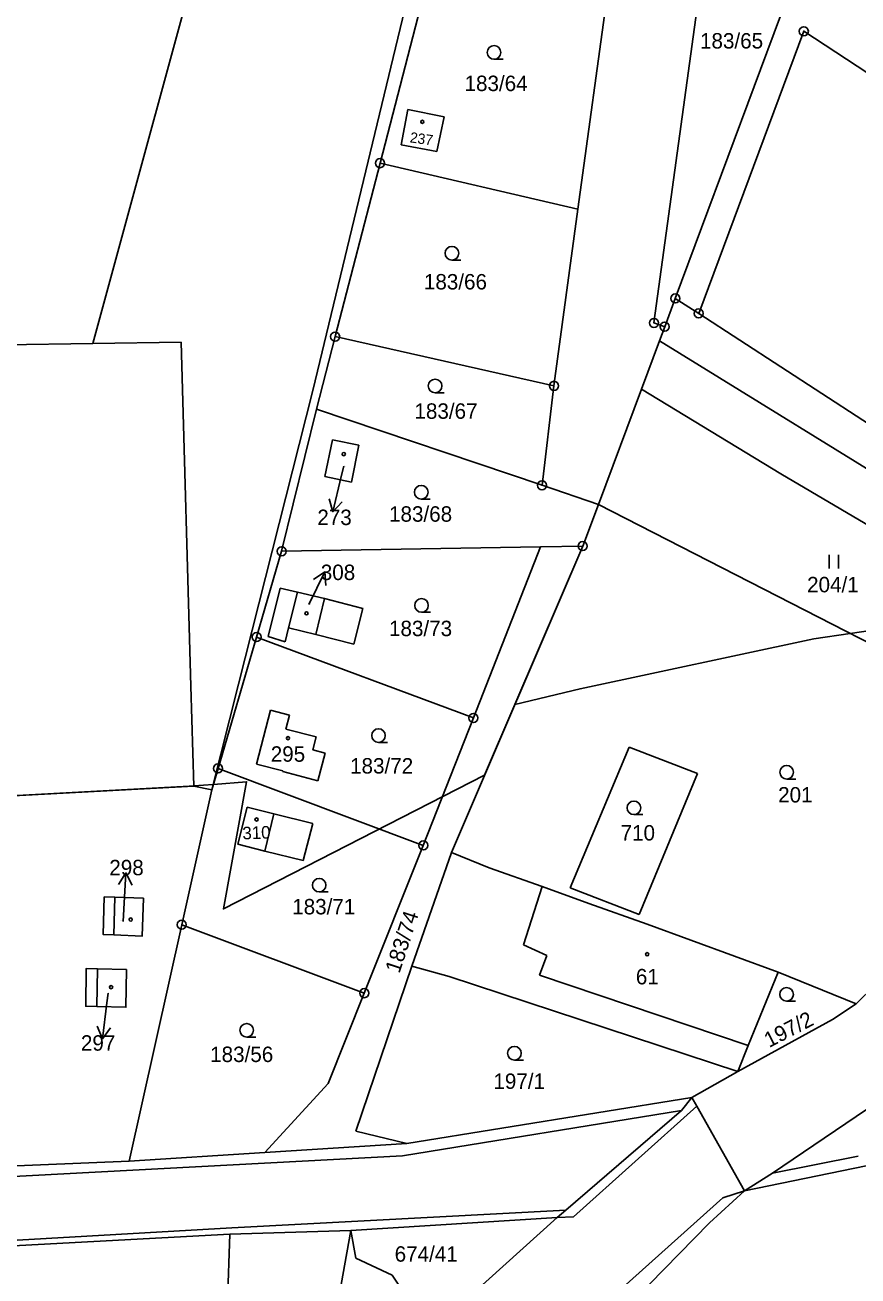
# Model space of a CAD drawing. Extents: x -747333 to -745433, y -1133152 to -1130600.
# Drawn here: x -746813.1 to -746721.3, y -1132285.5 to -1132147.6 of the extents above; entities that cross this region are included whole.
import ezdxf

# ---------------------------------------------------------------- set-up
doc = ezdxf.new("R2010")
doc.units = 0
for name, color, linetype in [('Vrstva 1', 7, 'Continuous'), ('Vrstva 16', 7, 'Continuous'), ('Vrstva 18', 7, 'Continuous'), ('Vrstva 19', 7, 'Continuous'), ('Vrstva 24', 7, 'Continuous'), ('Vrstva 25', 7, 'Continuous'), ('Vrstva 3', 7, 'Continuous'), ('Vrstva 37', 7, 'Continuous'), ('Vrstva 4', 7, 'Continuous'), ('Vrstva 52', 7, 'Continuous'), ('Vrstva 6', 7, 'Continuous')]:
    doc.layers.add(name, color=color, linetype=linetype)

msp = doc.modelspace()

# ---------------------------------------------------------------- linework, layer by layer
at = {"layer": 'Vrstva 1'}
for p, q in [((-746779.23, -1132193.32), (-746780.05, -1132197.37)), ((-746776.31, -1132193.91), (-746779.23, -1132193.32)), ((-746777.12, -1132197.98), (-746776.31, -1132193.91)), ((-746780.05, -1132197.37), (-746777.12, -1132197.98)), ((-746787.59, -1132215.05), (-746784.83, -1132205.6)), ((-746784.83, -1132205.6), (-746756.31, -1132205.11)), ((-746756.31, -1132205.11), (-746763.69, -1132223.97)), ((-746756.31, -1132205.11), (-746751.65, -1132205.03)), ((-746786.31, -1132214.99), (-746785, -1132209.67)), ((-746785, -1132209.67), (-746783.07, -1132210.11)), ((-746783.07, -1132210.11), (-746780.12, -1132210.8)), ((-746780.12, -1132210.8), (-746775.87, -1132211.89)), ((-746775.87, -1132211.89), (-746776.88, -1132215.82)), ((-746784.07, -1132214.03), (-746784.43, -1132215.59)), ((-746781.07, -1132214.77), (-746784.07, -1132214.03)), ((-746791.83, -1132229.53), (-746787.59, -1132215.05)), ((-746763.69, -1132223.97), (-746787.59, -1132215.05)), ((-746784.43, -1132215.59), (-746786.31, -1132214.99)), ((-746776.88, -1132215.82), (-746781.07, -1132214.77)), ((-746787.58, -1132229.04), (-746786.06, -1132223.12)), ((-746786.06, -1132223.12), (-746783.97, -1132223.66)), ((-746783.97, -1132223.66), (-746784.36, -1132225.19)), ((-746769.22, -1132238.01), (-746763.69, -1132223.97)), ((-746784.36, -1132225.19), (-746781.01, -1132226.05)), ((-746781.01, -1132226.05), (-746781.38, -1132227.48)), ((-746781.38, -1132227.48), (-746780.03, -1132227.83)), ((-746780.03, -1132227.83), (-746780.82, -1132230.88)), ((-746792.52, -1132231.9), (-746791.83, -1132229.53)), ((-746791.83, -1132229.53), (-746769.22, -1132238.01)), ((-746784.68, -1132229.78), (-746787.58, -1132229.04)), ((-746784.71, -1132229.88), (-746784.68, -1132229.78)), ((-746780.82, -1132230.88), (-746784.71, -1132229.88)), ((-746792.52, -1132231.9), (-746795.83, -1132246.75)), ((-746789.66, -1132237.89), (-746788.62, -1132233.78)), ((-746788.62, -1132233.78), (-746785.69, -1132234.52)), ((-746785.69, -1132234.52), (-746781.4, -1132235.6)), ((-746781.4, -1132235.6), (-746782.44, -1132239.69)), ((-746786.66, -1132238.64), (-746789.66, -1132237.89)), ((-746782.44, -1132239.69), (-746786.66, -1132238.64)), ((-746775.72, -1132254.29), (-746769.22, -1132238.01)), ((-746795.83, -1132246.75), (-746801.64, -1132272.79)), ((-746795.83, -1132246.75), (-746775.72, -1132254.29)), ((-746775.72, -1132254.29), (-746779.69, -1132264.25)), ((-746779.69, -1132264.25), (-746786.69, -1132271.84)), ((-746771.04, -1132270.84), (-746786.69, -1132271.84)), ((-746786.69, -1132271.84), (-746801.64, -1132272.79))]:
    msp.add_line(p, q, dxfattribs=at)
for points in [[(-746736.6, -1132128.06), (-746743.8, -1132180.44)], [(-746767.86, -1132139.21), (-746773.98, -1132162.83)], [(-746748.85, -1132143.55), (-746752.17, -1132167.89)], [(-746741.45, -1132177.74), (-746729.85, -1132146.61)], [(-746727.28, -1132148.3), (-746738.86, -1132179.39)], [(-746706, -1132162.26), (-746727.28, -1132148.3)], [(-746771.66, -1132160.8), (-746770.91, -1132156.92)], [(-746770.91, -1132156.92), (-746766.92, -1132157.72)], [(-746766.92, -1132157.72), (-746767.74, -1132161.56)], [(-746767.74, -1132161.56), (-746771.66, -1132160.8)], [(-746773.98, -1132162.83), (-746778.93, -1132181.95)], [(-746752.17, -1132167.89), (-746773.98, -1132162.83)], [(-746752.17, -1132167.89), (-746754.82, -1132187.37)], [(-746742.61, -1132180.85), (-746741.45, -1132177.74)], [(-746738.86, -1132179.39), (-746741.45, -1132177.74)], [(-746738.86, -1132179.39), (-746702.69, -1132202.89)], [(-746743.8, -1132180.44), (-746742.61, -1132180.85)], [(-746742.61, -1132180.85), (-746743.19, -1132182.42)], [(-746825.13, -1132182.99), (-746805.63, -1132182.7)], [(-746805.63, -1132182.7), (-746795.89, -1132182.56)], [(-746795.89, -1132182.56), (-746794.83, -1132220.45)], [(-746778.93, -1132181.95), (-746781, -1132189.93)], [(-746754.82, -1132187.37), (-746778.93, -1132181.95)], [(-746743.19, -1132182.42), (-746745.18, -1132187.75)], [(-746756.13, -1132198.33), (-746754.82, -1132187.37)], [(-746745.18, -1132187.75), (-746749.91, -1132200.43)], [(-746781, -1132189.93), (-746784.83, -1132205.6)], [(-746781, -1132189.93), (-746756.13, -1132198.33)], [(-746749.91, -1132200.43), (-746756.13, -1132198.33)], [(-746751.65, -1132205.03), (-746749.91, -1132200.43)], [(-746693.83, -1132229.18), (-746749.91, -1132200.43)], [(-746751.65, -1132205.03), (-746766.12, -1132238.78)], [(-746794.83, -1132220.45), (-746794.52, -1132231.47)], [(-746753.02, -1132242.69), (-746746.53, -1132227.19)], [(-746746.53, -1132227.19), (-746739, -1132230.07)], [(-746739, -1132230.07), (-746745.42, -1132245.64)], [(-746844.62, -1132234.18), (-746794.52, -1132231.47)], [(-746794.52, -1132231.47), (-746792.52, -1132231.9)], [(-746766.12, -1132238.78), (-746770.48, -1132251.33)], [(-746761.95, -1132240.48), (-746766.12, -1132238.78)], [(-746756.12, -1132242.54), (-746761.95, -1132240.48)], [(-746750.97, -1132244.4), (-746756.12, -1132242.54)], [(-746745.42, -1132245.64), (-746753.02, -1132242.69)], [(-746721.51, -1132255.46), (-746709.03, -1132243.21)], [(-746803.33, -1132247.87), (-746804.5, -1132247.82), (-746804.37, -1132243.68), (-746803.22, -1132243.72)], [(-746800.06, -1132243.84), (-746800.18, -1132248), (-746803.33, -1132247.87)], [(-746803.22, -1132243.72), (-746800.06, -1132243.84)], [(-746744.54, -1132246.69), (-746750.97, -1132244.4)], [(-746730.11, -1132251.98), (-746744.54, -1132246.69)], [(-746805.19, -1132255.76), (-746806.42, -1132255.73), (-746806.38, -1132251.58), (-746805.12, -1132251.61)], [(-746801.92, -1132251.69), (-746801.99, -1132255.84), (-746805.19, -1132255.76)], [(-746805.12, -1132251.61), (-746801.92, -1132251.69)], [(-746770.48, -1132251.33), (-746776.66, -1132269.51)], [(-746770.48, -1132251.33), (-746766.36, -1132252.44)], [(-746766.36, -1132252.44), (-746734.54, -1132262.91)], [(-746733.4, -1132260.05), (-746730.11, -1132251.98)], [(-746730.11, -1132251.98), (-746721.51, -1132255.46)], [(-746721.51, -1132255.46), (-746724.11, -1132257.19)], [(-746734.54, -1132262.91), (-746724.11, -1132257.19)], [(-746734.54, -1132262.91), (-746733.4, -1132260.05)], [(-746739.61, -1132265.77), (-746734.54, -1132262.91)], [(-746730.72, -1132274.13), (-746718.09, -1132265.55)], [(-746739.61, -1132265.77), (-746771.04, -1132270.84)], [(-746740.77, -1132267.23), (-746739.61, -1132265.77)], [(-746739.61, -1132265.77), (-746739.07, -1132266.74)], [(-746739.07, -1132266.74), (-746733.81, -1132276.07)], [(-746753.49, -1132278.19), (-746740.77, -1132267.23)], [(-746771.04, -1132270.84), (-746776.66, -1132269.51)], [(-746801.64, -1132272.79), (-746841.63, -1132274.45)], [(-746733.81, -1132276.07), (-746720.42, -1132273.3)], [(-746733.81, -1132276.07), (-746730.72, -1132274.13)], [(-746737.69, -1132279.59), (-746733.81, -1132276.07)], [(-746777.2, -1132280.46), (-746754.45, -1132279.02)], [(-746754.45, -1132279.02), (-746753.49, -1132278.19)], [(-746790.54, -1132280.83), (-746777.2, -1132280.46)], [(-746776.66, -1132283.5), (-746777.2, -1132280.46)], [(-746744.33, -1132286.38), (-746737.69, -1132279.59)], [(-746826.69, -1132282.8), (-746790.54, -1132280.83)], [(-746772.66, -1132285.36), (-746776.66, -1132283.5)], [(-746771.15, -1132287.59), (-746772.66, -1132285.36)]]:
    msp.add_lwpolyline(points, dxfattribs=at)
at = {"layer": 'Vrstva 16'}
for p, q in [((-746778.144735, -1132200.160253), (-746779.175042, -1132201.251567)), ((-746781.310878, -1132208.706273), (-746780.063977, -1132207.870966)), ((-746802.807702, -1132242.302254), (-746801.986115, -1132241.04627)), ((-746803.674118, -1132258.122681), (-746804.581052, -1132259.318494))]:
    msp.add_line(p, q, dxfattribs=at)
for points in [[(-746777.98, -1132196.22), (-746778.25, -1132197.36)], [(-746778.25, -1132197.36), (-746779.175042, -1132201.251567), (-746779.604073, -1132199.813363)], [(-746781.83, -1132211.46), (-746780.063977, -1132207.870966), (-746779.964991, -1132209.368531)], [(-746802.21, -1132245.04), (-746801.986115, -1132241.04627), (-746801.310053, -1132242.386211)], [(-746802.29, -1132246.38), (-746802.21, -1132245.04)], [(-746803.94, -1132254.29), (-746804.08, -1132255.35)], [(-746804.08, -1132255.35), (-746804.581052, -1132259.318494), (-746805.162303, -1132257.934786)]]:
    msp.add_lwpolyline(points, dxfattribs=at)
at = {"layer": 'Vrstva 24'}
for p, q in [((-746727.33, -1132148.3), (-746727.23, -1132148.3)), ((-746774.03, -1132162.83), (-746773.93, -1132162.83)), ((-746741.5, -1132177.74), (-746741.4, -1132177.74)), ((-746738.91, -1132179.39), (-746738.81, -1132179.39)), ((-746743.85, -1132180.44), (-746743.75, -1132180.44)), ((-746742.66, -1132180.85), (-746742.56, -1132180.85)), ((-746778.98, -1132181.95), (-746778.88, -1132181.95)), ((-746754.87, -1132187.37), (-746754.77, -1132187.37)), ((-746756.18, -1132198.33), (-746756.08, -1132198.33)), ((-746784.88, -1132205.6), (-746784.78, -1132205.6)), ((-746751.7, -1132205.03), (-746751.6, -1132205.03)), ((-746787.64, -1132215.05), (-746787.54, -1132215.05)), ((-746763.74, -1132223.97), (-746763.64, -1132223.97)), ((-746791.88, -1132229.53), (-746791.78, -1132229.53)), ((-746769.27, -1132238.01), (-746769.17, -1132238.01)), ((-746795.88, -1132246.75), (-746795.78, -1132246.75)), ((-746775.77, -1132254.29), (-746775.67, -1132254.29))]:
    msp.add_line(p, q, dxfattribs=at)
for centre in [(-746727.28, -1132148.3), (-746773.98, -1132162.83), (-746741.45, -1132177.74), (-746743.8, -1132180.44), (-746738.86, -1132179.39), (-746778.93, -1132181.95), (-746742.61, -1132180.85), (-746754.82, -1132187.37), (-746756.13, -1132198.33), (-746751.65, -1132205.03), (-746784.83, -1132205.6), (-746787.59, -1132215.05), (-746763.69, -1132223.97), (-746791.83, -1132229.53), (-746769.22, -1132238.01), (-746795.83, -1132246.75), (-746775.72, -1132254.29)]:
    msp.add_circle(centre, 0.499289, dxfattribs=at)
at = {"layer": 'Vrstva 25'}
for p, q in [((-746761.42, -1132151.38), (-746760.42, -1132151.38)), ((-746766.06, -1132173.51), (-746765.06, -1132173.51)), ((-746767.91, -1132188.13), (-746766.91, -1132188.13)), ((-746769.44, -1132199.84), (-746768.44, -1132199.84)), ((-746724.47, -1132206), (-746724.47, -1132207.5)), ((-746723.47, -1132207.5), (-746723.47, -1132206)), ((-746769.41, -1132212.32), (-746768.41, -1132212.32)), ((-746774.15, -1132226.66), (-746773.15, -1132226.66)), ((-746729.17, -1132230.7), (-746728.17, -1132230.7)), ((-746746.01, -1132234.62), (-746745.01, -1132234.62)), ((-746780.69, -1132243.14), (-746779.69, -1132243.14)), ((-746729.18, -1132255.17), (-746728.18, -1132255.17)), ((-746788.68, -1132259.13), (-746787.68, -1132259.13)), ((-746759.17, -1132261.66), (-746758.17, -1132261.66))]:
    msp.add_line(p, q, dxfattribs=at)
for centre, radius in [((-746761.42, -1132150.63), 0.75), ((-746769.32, -1132158.28), 0.174503), ((-746766.06, -1132172.76), 0.75), ((-746767.91, -1132187.38), 0.75), ((-746777.98, -1132194.89), 0.174503), ((-746769.44, -1132199.09), 0.75), ((-746769.41, -1132211.57), 0.75), ((-746782.09, -1132212.44), 0.174503), ((-746774.15, -1132225.91), 0.75), ((-746784.12, -1132226.19), 0.174503), ((-746729.17, -1132229.95), 0.75), ((-746746.01, -1132233.87), 0.75), ((-746787.59, -1132235.15), 0.174503), ((-746780.69, -1132242.39), 0.75), ((-746801.46, -1132246.18), 0.174503), ((-746744.54, -1132250), 0.174503), ((-746803.62, -1132253.63), 0.174503), ((-746729.18, -1132254.42), 0.75), ((-746788.68, -1132258.38), 0.75), ((-746759.17, -1132260.91), 0.75)]:
    msp.add_circle(centre, radius, dxfattribs=at)
at = {"layer": 'Vrstva 3'}
for points in [[(-746771.66, -1132160.8), (-746770.91, -1132156.92)], [(-746770.91, -1132156.92), (-746766.92, -1132157.72)], [(-746766.92, -1132157.72), (-746767.74, -1132161.56)], [(-746767.74, -1132161.56), (-746771.66, -1132160.8)], [(-746779.23, -1132193.32), (-746780.05, -1132197.37)], [(-746776.31, -1132193.91), (-746779.23, -1132193.32)], [(-746777.12, -1132197.98), (-746776.31, -1132193.91)], [(-746780.05, -1132197.37), (-746777.12, -1132197.98)], [(-746784.07, -1132214.03), (-746783.07, -1132210.11)], [(-746783.07, -1132210.11), (-746780.12, -1132210.8)], [(-746780.12, -1132210.8), (-746781.07, -1132214.77)], [(-746781.07, -1132214.77), (-746784.07, -1132214.03)], [(-746787.58, -1132229.04), (-746786.06, -1132223.12)], [(-746786.06, -1132223.12), (-746783.97, -1132223.66)], [(-746783.97, -1132223.66), (-746784.36, -1132225.19)], [(-746784.36, -1132225.19), (-746781.01, -1132226.05)], [(-746781.01, -1132226.05), (-746781.38, -1132227.48)], [(-746781.38, -1132227.48), (-746780.03, -1132227.83)], [(-746780.03, -1132227.83), (-746780.82, -1132230.88)], [(-746784.68, -1132229.78), (-746787.58, -1132229.04)], [(-746784.71, -1132229.88), (-746784.68, -1132229.78)], [(-746780.82, -1132230.88), (-746784.71, -1132229.88)], [(-746789.66, -1132237.89), (-746788.62, -1132233.78)], [(-746788.62, -1132233.78), (-746785.69, -1132234.52)], [(-746786.66, -1132238.64), (-746785.69, -1132234.52)], [(-746786.66, -1132238.64), (-746789.66, -1132237.89)], [(-746756.12, -1132242.54), (-746758.19, -1132248.97)], [(-746750.97, -1132244.4), (-746756.12, -1132242.54)], [(-746803.33, -1132247.87), (-746803.22, -1132243.72)], [(-746800.06, -1132243.84), (-746800.18, -1132248), (-746803.33, -1132247.87)], [(-746803.22, -1132243.72), (-746800.06, -1132243.84)], [(-746744.54, -1132246.69), (-746750.97, -1132244.4)], [(-746730.11, -1132251.98), (-746744.54, -1132246.69)], [(-746758.19, -1132248.97), (-746755.61, -1132250.15)], [(-746755.61, -1132250.15), (-746756.42, -1132252.29)], [(-746805.19, -1132255.76), (-746805.12, -1132251.61)], [(-746801.92, -1132251.69), (-746801.99, -1132255.84), (-746805.19, -1132255.76)], [(-746805.12, -1132251.61), (-746801.92, -1132251.69)], [(-746756.42, -1132252.29), (-746733.4, -1132260.05)], [(-746733.4, -1132260.05), (-746730.11, -1132251.98)]]:
    msp.add_lwpolyline(points, dxfattribs=at)
at = {"layer": 'Vrstva 37'}
for centre in [(-746769.32, -1132158.28), (-746777.98, -1132194.89), (-746782.09, -1132212.44), (-746784.12, -1132226.19), (-746787.59, -1132235.15), (-746801.46, -1132246.18), (-746744.54, -1132250), (-746803.62, -1132253.63)]:
    msp.add_circle(centre, 0.174503, dxfattribs=at)
at = {"layer": 'Vrstva 4'}
for p, q in [((-746784.07, -1132214.03), (-746783.07, -1132210.11)), ((-746780.12, -1132210.8), (-746781.07, -1132214.77)), ((-746786.66, -1132238.64), (-746785.69, -1132234.52))]:
    msp.add_line(p, q, dxfattribs=at)
for points in [[(-746756.12, -1132242.54), (-746758.19, -1132248.97)], [(-746803.33, -1132247.87), (-746803.22, -1132243.72)], [(-746758.19, -1132248.97), (-746755.61, -1132250.15)], [(-746755.61, -1132250.15), (-746756.42, -1132252.29)], [(-746805.19, -1132255.76), (-746805.12, -1132251.61)], [(-746756.42, -1132252.29), (-746733.4, -1132260.05)], [(-746739.07, -1132266.74), (-746752.66, -1132278.93)], [(-746771.51, -1132272.22), (-746740.77, -1132267.23)], [(-746853.8, -1132276.58), (-746771.51, -1132272.22)], [(-746730.72, -1132274.13), (-746721.28, -1132272.26)], [(-746753.49, -1132278.19), (-746790.3, -1132280.16)], [(-746752.66, -1132278.93), (-746754.45, -1132279.02)], [(-746790.3, -1132280.16), (-746826.79, -1132282.23)]]:
    msp.add_lwpolyline(points, dxfattribs=at)
at = {"layer": 'Vrstva 52'}
for points in [[(-746820.81, -1132085.58), (-746798.85, -1132085.43), (-746779.05, -1132085.29), (-746756.2, -1132085.13), (-746753.86, -1132085.11), (-746761.49, -1132114.56), (-746767.86, -1132139.21), (-746773.98, -1132162.83), (-746778.93, -1132181.95), (-746754.82, -1132187.37), (-746752.17, -1132167.89), (-746748.85, -1132143.55), (-746745.32, -1132117.64), (-746740.89, -1132085.03), (-746730.65, -1132084.95), (-746733.1, -1132102.66), (-746736.6, -1132128.06), (-746743.8, -1132180.44), (-746742.61, -1132180.85), (-746743.19, -1132182.42)], [(-746743.19, -1132182.42), (-746745.18, -1132187.75), (-746749.91, -1132200.43), (-746751.65, -1132205.03), (-746759.14, -1132222.5)], [(-746759.14, -1132222.5), (-746751.94, -1132220.75), (-746726.19, -1132215.25), (-746722.16, -1132214.66), (-746717.69, -1132214), (-746703.12, -1132212.78), (-746702.81, -1132212.75), (-746697.31, -1132211), (-746696.9, -1132210.96), (-746690.66, -1132210.29), (-746682, -1132209.38), (-746675.75, -1132208.13), (-746666.03, -1132206.19), (-746658.19, -1132204.63), (-746652.19, -1132204.25), (-746647.76, -1132202.77), (-746645.81, -1132202.12), (-746623.31, -1132196.5)], [(-746759.14, -1132222.5), (-746762.47, -1132230.28), (-746791.25, -1132245), (-746788.69, -1132231), (-746792.34, -1132231.29), (-746792.37, -1132231.29), (-746794.52, -1132231.46), (-746795.01, -1132231.5), (-746838.42, -1132233.84)]]:
    msp.add_lwpolyline(points, dxfattribs=at)
at = {"layer": 'Vrstva 6'}
for points in [[(-746778.25, -1132082.36), (-746805.63, -1132182.7)], [(-746781.38, -1132187.88), (-746766.7, -1132126.93)], [(-746682.41, -1132219.89), (-746743.19, -1132182.42)], [(-746789.57, -1132220.24), (-746781.38, -1132187.88)], [(-746729.82, -1132197.08), (-746745.18, -1132187.75)], [(-746700.07, -1132214.57), (-746729.82, -1132197.08)], [(-746792.52, -1132231.9), (-746789.57, -1132220.24)], [(-746736.22, -1132276.85), (-746733.81, -1132276.07)], [(-746773.04, -1132309.86), (-746736.22, -1132276.85)], [(-746754.45, -1132279.02), (-746773.55, -1132296.22)], [(-746777.2, -1132280.46), (-746782.33, -1132309.15)], [(-746791.31, -1132303.31), (-746790.54, -1132280.83)]]:
    msp.add_lwpolyline(points, dxfattribs=at)

# ---------------------------------------------------------------- texts
at = {"layer": 'Vrstva 16'}
for s, p in [('273', (-746780.891545, -1132202.71)), ('308', (-746780.51, -1132208.77)), ('298', (-746803.817405, -1132241.3)), ('297', (-746806.947405, -1132260.63))]:
    msp.add_text(s, height=1.7, dxfattribs=at).set_placement(p)
at = {"layer": 'Vrstva 18'}
for s, p in [('183/65', (-746738.72, -1132150.2)), ('183/64', (-746764.67, -1132154.89)), ('183/66', (-746769.15, -1132176.75)), ('183/67', (-746770.19, -1132191)), ('183/68', (-746772.99, -1132202.34)), ('204/1', (-746726.92, -1132210.12)), ('183/73', (-746772.993282, -1132214.95)), ('183/72', (-746777.283282, -1132230.09)), ('201', (-746730.11, -1132233.28)), ('710', (-746747.473812, -1132237.47)), ('183/71', (-746783.660547, -1132245.61)), ('183/56', (-746792.704664, -1132261.88)), ('197/1', (-746761.49, -1132264.84)), ('674/41', (-746772.37, -1132283.88))]:
    msp.add_text(s, height=1.7, dxfattribs=at).set_placement(p)
for s, rotation, p in [('183/74', 72, (-746771.847295, -1132252.187904)), ('197/2', 27.36558, (-746731.1, -1132260.34))]:
    msp.add_text(s, height=1.7, rotation=rotation, dxfattribs=at).set_placement(p)
at = {"layer": 'Vrstva 19'}
for s, height, rotation, p in [('237', 1.14, 352.01988, (-746770.75, -1132160.53)), ('310', 1.39, 2.04543, (-746789.127832, -1132237.355637))]:
    msp.add_text(s, height=height, rotation=rotation, dxfattribs=at).set_placement(p)
for s, height, p in [('273', 0.1, (-746777.98, -1132196.22)), ('308', 0.1, (-746781.83, -1132211.46)), ('295', 1.7, (-746786.027405, -1132228.79)), ('298', 0.1, (-746802.59, -1132246.42)), ('61', 1.7, (-746745.79, -1132253.32)), ('297', 0.1, (-746804.13, -1132254.27))]:
    msp.add_text(s, height=height, dxfattribs=at).set_placement(p)

doc.saveas('drawing.dxf')
